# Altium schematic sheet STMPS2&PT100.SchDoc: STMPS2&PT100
size A4; Date: Not used; ApprovedBy: Not used; CheckedBy: Not used; Author: Not used; CompanyName: STMicroelectronics; DrawnBy: Not used; Engineer: Not used; Organization: Not used; Address1: Not used; Address2: Not used; Address3: Not used; Address4: Not used; DocumentNumber: Not used; Revision: Not used; SheetNumber: 16; SheetTotal: 23
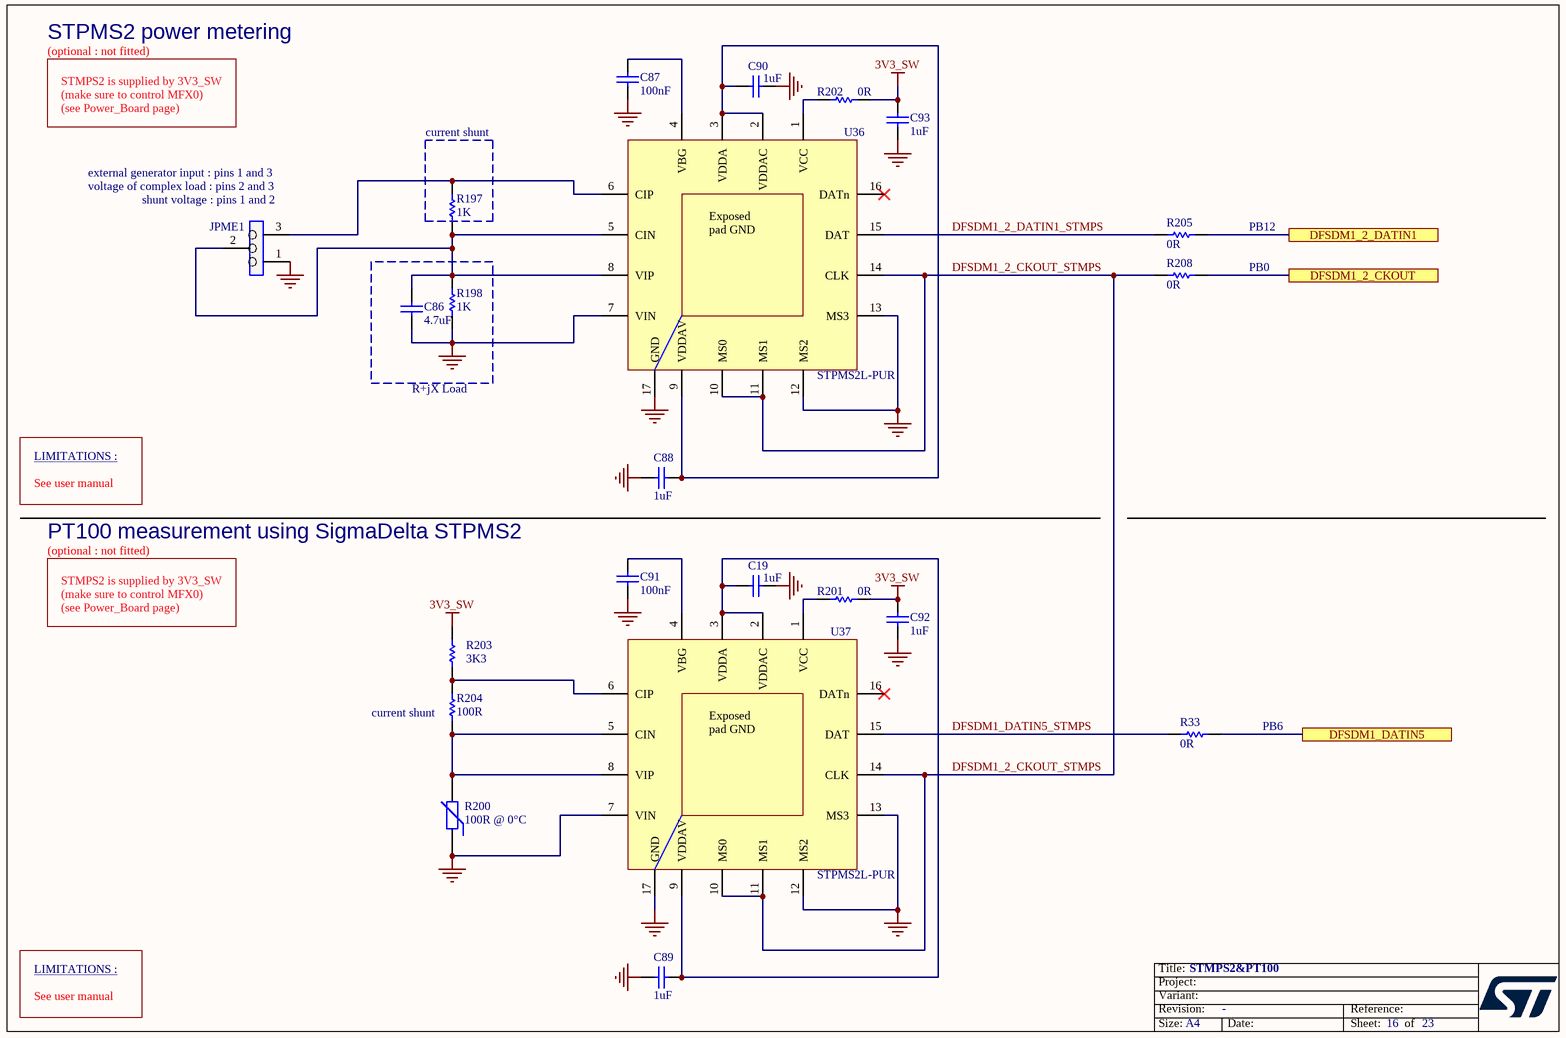
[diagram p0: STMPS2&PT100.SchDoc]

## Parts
C19  value 1uF  [C0402]  (hidden comment: Capacitor)
C86  value 4.7uF  [C0402]  (hidden comment: Capacitor)
C87  value 100nF  [C0402]  (hidden comment: Capacitor)
C88  value 1uF  [C0603]  (hidden comment: Capacitor)
C89  value 1uF  [C0603]  (hidden comment: Capacitor)
C90  value 1uF  [C0402]  (hidden comment: Capacitor)
C91  value 100nF  [C0402]  (hidden comment: Capacitor)
C92  value 1uF  [C0402]  (hidden comment: Capacitor)
C93  value 1uF  [C0402]  (hidden comment: Capacitor)
JPME1  Jumper_Header 3x1  [CON_SAMTEC_TSW-103-07-F-S]  (value not drawn)
R33  value 0R  [R0402]  (hidden comment: Resistor)
R197  value 1K  [R0603]  (hidden comment: Resistor)
R198  value 1K  [R0603]  (hidden comment: Resistor)
R200  value 100R @ 0°C  [R0603_H0P45]  (hidden comment: PT100)
R201  value 0R  [R0603]  (hidden comment: Resistor)
R202  value 0R  [R0603]  (hidden comment: Resistor)
R203  value 3K3  [R0603]  (hidden comment: Resistor)
R204  value 100R  [R0603]  (hidden comment: Resistor)
R205  value 0R  [R0402]  (hidden comment: Resistor)
R208  value 0R  [R0402]  (hidden comment: Resistor)
U36  STPMS2L-PUR  [ICC_QFN16-EPAD_4X4_P065]
U37  STPMS2L-PUR  [ICC_QFN16-EPAD_4X4_P065]

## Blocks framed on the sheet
current shunt: R197

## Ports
DFSDM1_2_CKOUT, DFSDM1_2_DATIN1, DFSDM1_DATIN5

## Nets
3V3_SW: C92.1 C93.1 R201.2 R202.2 R203.2
GND: C19.1 C86.1 C87.1 C88.1 C89.1 C90.1 C91.1 C92.2 C93.2 JPME1.1 R198.1 R200.1 U36.7(VIN) U36.12(MS2) U36.13(MS3) U36.17(GND) U37.7(VIN) U37.12(MS2) U37.13(MS3) U37.17(GND)
DFSDM1_2_CKOUT: R208.2 ; port DFSDM1_2_CKOUT
DFSDM1_2_CKOUT_STMPS: R208.1 U36.10(MS0) U36.11(MS1) U36.14(CLK) U37.10(MS0) U37.11(MS1) U37.14(CLK)
DFSDM1_2_DATIN1: R205.2 ; port DFSDM1_2_DATIN1
DFSDM1_2_DATIN1_STMPS: R205.1 U36.15(DAT)
DFSDM1_DATIN5: R33.2 ; port DFSDM1_DATIN5
DFSDM1_DATIN5_STMPS: R33.1 U37.15(DAT)
NetC19_2: C19.2 C89.2 U37.2(VDDAC) U37.3(VDDA) U37.9(VDDAV)
NetC86_2: C86.2 JPME1.2 R197.1 R198.2 U36.5(CIN) U36.8(VIP)
NetC87_2: C87.2 U36.4(VBG)
NetC88_2: C88.2 C90.2 U36.2(VDDAC) U36.3(VDDA) U36.9(VDDAV)
NetC91_2: C91.2 U37.4(VBG)
NetJPME1_3: JPME1.3 R197.2 U36.6(CIP)
NetR200_2: R200.2 R204.1 U37.5(CIN) U37.8(VIP)
NetR201_1: R201.1 U37.1(VCC)
NetR202_1: R202.1 U36.1(VCC)
NetR203_1: R203.1 R204.2 U37.6(CIP)

Not connected (* = marked no-connect by the designer): U36 16(DATn)*; U37 16(DATn)*

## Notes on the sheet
- STPMS2 power metering
- (optional : not fitted)
- STMPS2 is supplied by 3V3_SW
  (make sure to control MFX0)
  (see Power_Board page)
- external generator input : pins 1 and 3
- (near JPME1) voltage of complex load : pins 2 and 3
- (near JPME1) shunt voltage : pins 1 and 2
- PB12
- PB0
- R+jX Load
- LIMITATIONS :
- See user manual
- PT100 measurement using SigmaDelta STPMS2
- (near R204) current shunt
- PB6

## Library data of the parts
C19 C90 C92 C93 = MCD-00095: Capacitor, MLCC, 1uF, 6V3, X5R, 10%, 0402, T=0,5mm; Manufacturer_Part_Number: GRM155R61E105KA12; Manufacturer: MURATA; Alternate_Manufacturer_Part_Number: GRM155R60J105KE19; Part_Preference: Recommended; Provided_By: SUBCO; ECCN_US: EAR99; ECCN_EU: NEC; Component_Country_Of_Origin: Japan°°; ID: 2772; Order_Code_RS: 2218855; ShowFields: YES
C86 = MCD-01356: Capacitor, MLCC, 4.7uF, 6V3, X5R, 20%, 0402, T=0,5mm; Manufacturer_Part_Number: GRM155R60J475ME47; Manufacturer: MURATA; Part_Preference: Recommended; ECCN_US: EAR99; ECCN_EU: NEC; Provided_By: SUBCO; Component_Country_Of_Origin: Japan°°; ID: 3456; Order_Code_RS: 814-5230; ShowFields: YES
C87 C91 = MCD-00006: Capacitor, MLCC, 100nF, 16V, X7R, 10%, 0402, T=0.5mm; Manufacturer_Part_Number: CC0402KRX7R7BB104; Manufacturer: YAGEO; Alternate_Manufacturer_Part_Number: GCM155R71C104KA55D; Alternate_Manufacturer: MURATA; Part_Preference: Recommended; Partial_Alternate_Internal_Part_Number: MCD-03299; Provided_By: SUBCO; ECCN_US: EAR99; ECCN_EU: NEC; Component_Country_Of_Origin: China; ID: 2474; Order_Code_RS: 9402047; ShowFields: YES
C88 C89 = MCD-00010: Capacitor, MLCC, 1uF, 16V, X5R, 10%, 0603, T=0,8mm; Manufacturer_Part_Number: CC0603KRX5R7BB105; Manufacturer: YAGEO; Part_Preference: Recommended; Provided_By: SUBCO; ECCN_US: EAR99; ECCN_EU: NEC; Component_Country_Of_Origin: China; ID: 2470; Order_Code_RS: 2370680; ShowFields: YES
JPME1 = MCD-00111: Header, 3x1, 2,54mm, VR, TH, Height 5.84mm/2.54mm; Manufacturer_Part_Number: TSW-103-07-F-S; Manufacturer: SAMTEC; Part_Type: Connector; Part_Preference: Recommended; Provided_By: SUBCO; ECCN_US: EAR99; ECCN_EU: NEC; Component_Country_Of_Origin: China, Costa Rica, Malaysia, USA, Vietnam; ID: 2760; Order_Code_RS: 161-2248; ShowFields: YES
R33 R205 R208 = MCD-00052: Resistor,0R,0402,5%,1/16W; Manufacturer_Part_Number: RC0402JR-070RL; Manufacturer: YAGEO; Part_Preference: Recommended; Provided_By: SUBCO; ECCN_US: EAR99; ECCN_EU: NEC; Component_Country_Of_Origin: China; ID: 2540; Order_Code_RS: 9232516RL; ShowFields: YES
R197 R198 = MCD-00070: Resistor,1K,0603,1%,1/10W; Manufacturer_Part_Number: RC0603FR-071KL; Manufacturer: YAGEO; Part_Preference: Recommended; Provided_By: SUBCO; ECCN_US: EAR99; ECCN_EU: NEC; Component_Country_Of_Origin: China; ID: 2522; Order_Code_RS: 9238484RL; ShowFields: YES
R200 = MCD-00680: Resistor, SMD PTS 100ohm @ 0°C Flat Chip Temperature Sensor; Manufacturer_Part_Number: PTS060301B100RP100; Manufacturer: VISHAY; Part_Preference: Recommended; Provided_By: SUBCO; ECCN_US: EAR99; ECCN_EU: NEC; Component_Country_Of_Origin: Germany; ID: 3064; Order_Code_RS: 179-3948; ShowFields: YES
R201 R202 = MCD-00056: Resistor,0R,0603,5%,1/10W; Manufacturer_Part_Number: RC0603JR-070RL; Manufacturer: YAGEO; Part_Preference: Recommended; Provided_By: SUBCO; ECCN_US: EAR99; ECCN_EU: NEC; Component_Country_Of_Origin: China; ID: 2536; Order_Code_RS: 9233130RL; ShowFields: YES
R203 = MCD-00352: Resistor,3K3,0603,1%,1/10W; Manufacturer_Part_Number: RC0603FR-073K3L; Manufacturer: YAGEO; Part_Preference: Recommended; Provided_By: SUBCO; ECCN_US: EAR99; ECCN_EU: NEC; Component_Country_Of_Origin: China; ID: 2927; ShowFields: YES
R204 = MCD-00224: Resistor,100R,0603,1%,1/10W; Manufacturer_Part_Number: RC0603FR-07100RL; Manufacturer: YAGEO; Part_Preference: Recommended; Provided_By: SUBCO; ECCN_US: EAR99; ECCN_EU: NEC; Component_Country_Of_Origin: China; ID: 2643; ShowFields: YES
U36 U37 = MCD-00681: Smart sensor II dual-channel 1-bit, 4 MHz, second-order sigmadelta modulator with embedded PGLNA; Part_Type: IC; Manufacturer: STMICROELECTRONICS; BMS_Part_Number: 9177717; Manufacturer_HQ_COO: EU; Part_Preference: Recommended; Provided_By: SUBCO with ST control; ECCN_US: EAR99; ECCN_EU: NEC; Component_Country_Of_Origin: Malaysia; ID: 3063; ShowFields: YES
